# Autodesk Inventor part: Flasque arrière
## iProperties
Author: Philippe
Shininess: 20.0
Angle Display Precision: 2
Document Length Units: 11269
Document Angle Units: 11283
Document Time Units: 11279
Document Mass Units: 11290
Document Length Units Precision: 3
Document Angle Units Precision: 2
Compacted: False
PropertySet Name: _Private Model Information
Created: 2002-06
Part Number: Flasque arrière
Material: A-S13
Document SubType Name: Modélisation
Designer: Philippe
Control State: 0
Master: False
Checked Out: False
PropertySet Name: Design Tracking Control
Density: 2.71
Volumn: 10.707481322186645
Area: 92.01607629607588
PropertySet Name: Model Information
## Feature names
1. Révolution1:Enveloppe [Revolution]
2. Extrusion1:Percage central
3. Chanfrein1:Portée roulement [Chamfer]
4. Congé1:Moyeu [Fillet]
5. Extrusion2:Bossage d'assemblage
6. Extrusion4:Dégagement bossage
7. Perçage1:Taraudage d'assemblage [Hole]
8. Réseau circulaire1:Assemblage [Circular Pattern]
9. Congé3:Assemblage [Fillet]
10. Extrusion5:Passage fils
11. Extrusion6:Passage fils
12. Extrusion7:Empreinte marquage
13. Congé2:Empreinte marquage [Fillet]
14. Chanfrein2:Taraudages [Chamfer]
15. Extrusion8:Alvéoles
16. Réseau circulaire2:Alvéoles [Circular Pattern]
